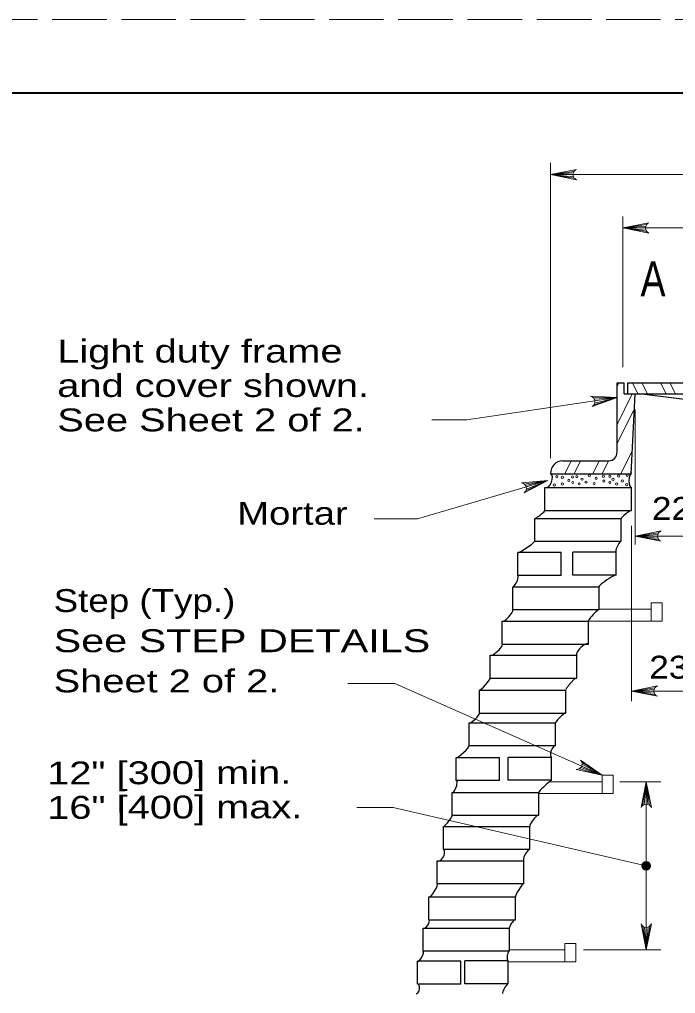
# Model space of a CAD drawing. Extents: x 1083.1 to 1117.1, y 697.4 to 741.4.
# Drawn here: x 1094.35 to 1098.82, y 734.71 to 741.35 of the extents above; entities that cross this region are included whole.
import ezdxf

# ---------------------------------------------------------------- set-up
doc = ezdxf.new("R2010")
doc.units = 0
doc.header["$LTSCALE"] = 0.062
doc.linetypes.add('LONG_DASHED', pattern=[7.5, 6, -1.5])
doc.layers.add('1', color=7, linetype='Continuous', lineweight=13)

msp = doc.modelspace()

# ---------------------------------------------------------------- hatches: boundary and pattern name
at = {"layer": '1'}
msp.add_hatch(color=256, dxfattribs=at).paths.add_polyline_path([(1098.6497, 735.5823, 1), (1098.5907, 735.5823, 1)])

# ---------------------------------------------------------------- linework, layer by layer
at = {"layer": '1', "lineweight": 25}
for p, q in [((1085.12642, 740.85408), (1116.62642, 740.85408)), ((1098.42183, 738.40442), (1098.42183, 738.87625)), ((1098.42183, 738.87625), (1098.4705, 738.87625)), ((1098.4705, 738.80017), (1098.4705, 738.87625)), ((1098.49483, 738.87625), (1100.443, 738.87625)), ((1098.49483, 738.80017), (1098.49483, 738.87625)), ((1098.4705, 738.80017), (1099.43358, 738.80017)), ((1098.51775, 738.25633), (1098.54433, 738.80017)), ((1099.431, 738.692), (1098.57267, 738.80017)), ((1098.051, 738.34442), (1098.36517, 738.34442)), ((1097.96783, 738.25633), (1098.51917, 738.25633)), ((1098.51208, 738.25633), (1098.51917, 738.27067)), ((1098.51917, 738.00592), (1098.51917, 738.16192)), ((1097.93, 738.00592), (1098.51917, 738.00592)), ((1098.44917, 737.79567), (1098.44917, 737.95158)), ((1097.86, 737.79567), (1098.44917, 737.79567)), ((1098.0405, 737.71808), (1097.74592, 737.71808)), ((1097.74592, 737.56217), (1097.74592, 737.71808)), ((1098.0405, 737.56217), (1098.0405, 737.71808)), ((1098.41458, 737.72033), (1098.11992, 737.72033)), ((1098.11992, 737.56442), (1098.11992, 737.72033)), ((1098.41458, 737.56442), (1098.41458, 737.72033)), ((1098.0405, 737.56217), (1097.74592, 737.56217)), ((1098.41458, 737.56442), (1098.11992, 737.56442)), ((1098.29975, 737.329), (1098.29975, 737.48492)), ((1097.7105, 737.329), (1098.29975, 737.329)), ((1098.22783, 737.09467), (1098.22783, 737.25058)), ((1097.63867, 737.09467), (1098.22783, 737.09467)), ((1098.1465, 736.86233), (1098.1465, 737.01825)), ((1097.55725, 736.86233), (1098.1465, 736.86233)), ((1098.07275, 736.62392), (1098.07275, 736.77992)), ((1097.4835, 736.62392), (1098.07275, 736.62392)), ((1098.00275, 736.40167), (1098.00275, 736.55758)), ((1097.4135, 736.40167), (1098.00275, 736.40167)), ((1097.62025, 736.31933), (1097.32567, 736.31933)), ((1097.32567, 736.16333), (1097.32567, 736.31933)), ((1097.62025, 736.16333), (1097.62025, 736.31933)), ((1097.97483, 736.32142), (1097.68025, 736.32142)), ((1097.68025, 736.16542), (1097.68025, 736.32142)), ((1097.97483, 736.16542), (1097.97483, 736.32142)), ((1097.62025, 736.16333), (1097.32567, 736.16333)), ((1097.97483, 736.16542), (1097.68025, 736.16542)), ((1097.88733, 735.92692), (1097.88733, 736.08292)), ((1097.29808, 735.92692), (1097.88733, 735.92692)), ((1097.82683, 735.69458), (1097.82683, 735.85058)), ((1097.23758, 735.69458), (1097.82683, 735.69458)), ((1097.78517, 735.46025), (1097.78517, 735.61625)), ((1097.19592, 735.46025), (1097.78517, 735.46025)), ((1097.72842, 735.21392), (1097.72842, 735.36992)), ((1097.13917, 735.21392), (1097.72842, 735.21392)), ((1097.68867, 735.00158), (1097.68867, 735.15758)), ((1097.0995, 735.00158), (1097.68867, 735.00158)), ((1097.67908, 734.934), (1097.3845, 734.934)), ((1097.3845, 734.778), (1097.3845, 734.934)), ((1097.67908, 734.778), (1097.67908, 734.934)), ((1097.35575, 734.9315), (1097.06108, 734.9315)), ((1097.06108, 734.77558), (1097.06108, 734.9315)), ((1097.35575, 734.77558), (1097.35575, 734.9315)), ((1097.35575, 734.77558), (1097.06108, 734.77558)), ((1097.67908, 734.778), (1097.3845, 734.778))]:
    msp.add_line(p, q, dxfattribs=at)
at = {"layer": '1'}
for p, q in [((1097.96783, 738.36233), (1097.96783, 740.376)), ((1098.128, 740.31817), (1097.96783, 740.29575)), ((1098.12258, 740.30708), (1097.96783, 740.29575)), ((1097.96783, 740.29575), (1099.78475, 740.29575)), ((1098.121, 740.29575), (1097.96783, 740.29575)), ((1098.12383, 740.28133), (1097.96783, 740.29575)), ((1098.12992, 740.27092), (1097.96783, 740.29575)), ((1098.46192, 738.98225), (1098.46192, 740.01133)), ((1098.62217, 739.95508), (1098.46192, 739.93267)), ((1098.61675, 739.944), (1098.46192, 739.93267)), ((1098.61508, 739.93267), (1098.46192, 739.93267)), ((1098.61792, 739.91825), (1098.46192, 739.93267)), ((1098.624, 739.90792), (1098.46192, 739.93267)), ((1098.42183, 738.85092), (1098.43433, 738.87625)), ((1098.56417, 738.80017), (1098.52658, 738.87625)), ((1098.628, 738.80017), (1098.5905, 738.87625)), ((1098.75575, 738.80017), (1098.71825, 738.87625)), ((1098.81967, 738.80017), (1098.78217, 738.87625)), ((1098.42183, 738.59167), (1098.52458, 738.80017)), ((1098.26, 738.77375), (1098.42183, 738.77483)), ((1098.265, 738.72675), (1098.42183, 738.77483)), ((1098.267, 738.7635), (1098.42183, 738.77483)), ((1098.26958, 738.73792), (1098.42183, 738.77483)), ((1098.27033, 738.75258), (1098.42183, 738.77483)), ((1098.42183, 738.462), (1098.5395, 738.70075)), ((1098.54433, 738.69408), (1098.54433, 737.77375)), ((1098.44825, 738.25633), (1098.52542, 738.41292)), ((1098.06492, 738.25633), (1098.10833, 738.34442)), ((1098.12883, 738.25633), (1098.17225, 738.34442)), ((1098.25658, 738.25633), (1098.3, 738.34442)), ((1098.3205, 738.25633), (1098.36392, 738.34442)), ((1097.78875, 738.18575), (1097.94892, 738.20908)), ((1097.79708, 738.17658), (1097.94892, 738.20908)), ((1097.80017, 738.13992), (1097.94892, 738.20908)), ((1097.80183, 738.16617), (1097.94892, 738.20908)), ((1097.80317, 738.15158), (1097.94892, 738.20908)), ((1098.51917, 737.89992), (1098.51917, 736.70442)), ((1098.70458, 737.85292), (1098.54433, 737.8305)), ((1098.69917, 737.84183), (1098.54433, 737.8305)), ((1098.6975, 737.8305), (1098.54433, 737.8305)), ((1098.70033, 737.81608), (1098.54433, 737.8305)), ((1098.70642, 737.80567), (1098.54433, 737.8305)), ((1098.54433, 737.8305), (1100.39208, 737.8305)), ((1098.29975, 737.33133), (1098.6535, 737.33133)), ((1098.6535, 737.25), (1098.6535, 737.37533)), ((1098.729, 737.37533), (1098.6535, 737.37533)), ((1098.729, 737.25), (1098.729, 737.37533)), ((1098.22783, 737.25), (1098.729, 737.25)), ((1098.67942, 736.79592), (1098.51917, 736.77342)), ((1098.674, 736.78475), (1098.51917, 736.77342)), ((1098.67233, 736.77342), (1098.51917, 736.77342)), ((1098.67517, 736.75908), (1098.51917, 736.77342)), ((1098.68133, 736.74867), (1098.51917, 736.77342)), ((1098.51917, 736.77342), (1100.41867, 736.77342)), ((1098.17992, 736.26142), (1098.32008, 736.19958)), ((1098.18175, 736.28775), (1098.32008, 736.19958)), ((1098.18317, 736.27575), (1098.32008, 736.19958)), ((1098.16442, 736.24375), (1098.32008, 736.19958)), ((1098.17383, 736.25175), (1098.32008, 736.19958)), ((1098.32008, 736.07425), (1098.32008, 736.19958)), ((1098.39558, 736.19958), (1098.32008, 736.19958)), ((1098.39558, 736.07425), (1098.39558, 736.19958)), ((1097.9605, 736.15558), (1098.32008, 736.15558)), ((1098.4415, 736.15558), (1098.72033, 736.15558)), ((1098.59542, 735.9935), (1098.62017, 736.15558)), ((1098.60583, 735.99958), (1098.62017, 736.15558)), ((1098.62017, 736.15558), (1098.62017, 735.009)), ((1098.62017, 736.00242), (1098.62017, 736.15558)), ((1098.6315, 736.00083), (1098.62017, 736.15558)), ((1098.64258, 735.99533), (1098.62017, 736.15558)), ((1097.88733, 736.07425), (1098.39558, 736.07425)), ((1098.59775, 735.16925), (1098.62017, 735.009)), ((1098.60883, 735.16383), (1098.62017, 735.009)), ((1098.645, 735.17117), (1098.62017, 735.009)), ((1098.63458, 735.165), (1098.62017, 735.009)), ((1098.62017, 735.16217), (1098.62017, 735.009)), ((1097.68867, 735.009), (1098.06525, 735.009)), ((1098.06525, 734.92767), (1098.06525, 735.05292)), ((1098.14075, 735.05292), (1098.06525, 735.05292)), ((1098.14075, 734.92767), (1098.14075, 735.05292)), ((1098.19317, 735.009), (1098.72033, 735.009)), ((1097.67908, 734.92767), (1098.14075, 734.92767))]:
    msp.add_line(p, q, dxfattribs=at)
at = {"layer": '1', "linetype": 'LONG_DASHED'}
msp.add_lwpolyline([(1083.12642, 719.35408), (1117.12642, 719.35408), (1117.12642, 741.35408), (1083.12642, 741.35408)], close=True, dxfattribs=at)
at = {"layer": '1', "lineweight": 40}
msp.add_lwpolyline([(1085.12642, 740.85408), (1116.62642, 740.85408), (1116.62642, 719.85408), (1085.12642, 719.85408)], close=True, dxfattribs=at)
at = {"layer": '1'}
for points in [[(1098.14483, 740.26033), (1097.96783, 740.29575), (1098.14483, 740.33117)], [(1098.63892, 739.89725), (1098.46192, 739.93267), (1098.63892, 739.96808)], [(1098.46192, 739.93267), (1099.79092, 739.93267), (1100.46742, 739.93267)], [(1098.42183, 738.77483), (1097.39708, 738.62283), (1097.15817, 738.62283)], [(1098.25183, 738.71408), (1098.42183, 738.77483), (1098.24158, 738.78417)], [(1097.94892, 738.20908), (1097.06192, 737.94908), (1096.76567, 737.94908)], [(1097.78892, 738.1255), (1097.94892, 738.20908), (1097.76908, 738.1935)], [(1098.72133, 737.79508), (1098.54433, 737.8305), (1098.72133, 737.86592)], [(1098.32008, 736.19958), (1096.90725, 736.82575), (1096.58683, 736.82575)], [(1098.69617, 736.73808), (1098.51917, 736.77342), (1098.69617, 736.80883)], [(1098.17242, 736.30342), (1098.32008, 736.19958), (1098.14383, 736.23867)], [(1098.58483, 735.97858), (1098.62017, 736.15558), (1098.65558, 735.97858)], [(1098.62017, 735.58233), (1096.89433, 735.979), (1096.64783, 735.979)], [(1098.65558, 735.186), (1098.62017, 735.009), (1098.58483, 735.186)]]:
    msp.add_lwpolyline(points, dxfattribs=at)
at = {"layer": '1', "lineweight": 25}
for points in [[(1097.93, 738.00592), (1097.93, 738.16192), (1098.51917, 738.16192)], [(1097.86, 737.79567), (1097.86, 737.95158), (1098.44917, 737.95158)], [(1097.7105, 737.329), (1097.7105, 737.48492), (1098.29975, 737.48492)], [(1097.63867, 737.09467), (1097.63867, 737.25058), (1098.22783, 737.25058)], [(1097.55725, 736.86233), (1097.55725, 737.01825), (1098.1465, 737.01825)], [(1097.4835, 736.62392), (1097.4835, 736.77992), (1098.07275, 736.77992)], [(1097.4135, 736.40167), (1097.4135, 736.55758), (1098.00275, 736.55758)], [(1097.29808, 735.92692), (1097.29808, 736.08292), (1097.88733, 736.08292)], [(1097.23758, 735.69458), (1097.23758, 735.85058), (1097.82683, 735.85058)], [(1097.19592, 735.46025), (1097.19592, 735.61625), (1097.78517, 735.61625)], [(1097.13917, 735.21392), (1097.13917, 735.36992), (1097.72842, 735.36992)], [(1097.0995, 735.00158), (1097.0995, 735.15758), (1097.68867, 735.15758)]]:
    msp.add_lwpolyline(points, dxfattribs=at)
at = {"layer": '1'}
msp.add_circle((1098.6202, 735.5823), 0.0295, dxfattribs=at)
for centre, start, end in [((1098.15909, 740.29577), 112.08782, 247.91395), ((1098.65319, 739.93272), 112.08782, 247.91395), ((1098.23257, 738.74707), 300.45401, 76.28014), ((1097.76523, 738.15556), 308.35015, 84.17628), ((1098.73562, 737.83052), 112.08782, 247.91395), ((1098.7105, 736.77349), 112.08782, 247.91395), ((1098.14503, 736.27679), 268.26852, 44.09464), ((1098.62024, 735.96432), 22.08782, 157.91395), ((1098.62016, 735.20029), 202.08782, 337.91395)]:
    msp.add_arc(centre, 0.0382, start, end, dxfattribs=at)
at = {"layer": '1', "lineweight": 25}
for centre, major_axis, ratio, start_param, end_param in [((1098.3652, 738.40439), (0, -0.05997), 0.944544, 0.000001, 1.5707952), ((1098.05103, 738.2563), (0, 0.08813), 0.944544, 0.0000048, 1.5708011), ((1097.94888, 738.2091), (0.01807, 0.04755), 0.550574, 3.1091398, 6.2507324), ((1098.5192, 738.2091), (0, -0.0472), 0.356664, 3.1415929, 6.2831855), ((1097.89497, 737.97876), (0.03498, 0.0272), 0.123309, 3.1347753, 6.276368), ((1098.4842, 737.97877), (-0.03499, -0.02719), 0.095152, 3.1363648, 6.2779574), ((1097.80295, 737.75688), (0.05701, 0.03878), 0.08505, 3.1371461, 6.2787387), ((1098.43189, 737.75799), (-0.01723, -0.03769), 0.223335, 3.131028, 6.2726207), ((1097.72822, 737.52355), (0.01758, 0.03869), 0.261975, 3.1289792, 6.2705719), ((1098.35716, 737.52466), (-0.05738, -0.03979), 0.123692, 3.1350238, 6.2766165), ((1097.67457, 737.28977), (0.03579, 0.03934), 0.255117, 3.1260199, 6.2676126), ((1098.26381, 737.28978), (-0.03589, -0.03924), 0.153621, 3.1326147, 6.2742074), ((1097.59795, 737.05644), (0.04053, 0.03834), 0.248819, 3.1265579, 6.2681506), ((1098.18719, 737.05644), (0.04038, 0.03851), 0.348106, 6.2607285, 9.4023212), ((1097.52039, 736.8211), (0.03686, 0.04122), 0.109562, 3.1352712, 6.2768638), ((1097.4485, 736.59077), (0.03491, 0.03328), 0.214158, 3.1288563, 6.2704489), ((1098.03774, 736.59077), (-0.03496, -0.03322), 0.136714, 3.1336877, 6.2752804), ((1097.36957, 736.36047), (0.04388, 0.04122), 0.144657, 3.1332208, 6.2748134), ((1097.98881, 736.36151), (-0.01364, -0.04023), 0.407354, 3.1235301, 6.2651227), ((1097.31187, 736.12314), (-0.01358, -0.0403), 0.335589, 6.2693556, 9.4109483), ((1097.93111, 736.12417), (-0.04376, -0.04127), 0.064605, 3.137914, 6.2795067), ((1097.85707, 735.88876), (-0.03017, -0.03827), 0.209512, 3.1292724, 6.2708651), ((1097.26784, 735.88876), (0.03023, 0.03822), 0.136372, 3.1337805, 6.2753732), ((1097.21676, 735.65543), (0.02002, 0.03962), 0.541644, 3.1041747, 6.2457674), ((1097.80599, 735.65543), (-0.02067, -0.03927), 0.264991, 3.1276914, 6.2692841), ((1097.16757, 735.41508), (0.02825, 0.04528), 0.223655, 3.1291999, 6.2707925), ((1097.75681, 735.41508), (-0.02834, -0.04523), 0.13218, 3.1345117, 6.2761043), ((1097.11933, 735.18575), (0.01952, 0.02843), 0.429767, 3.112728, 6.2543206), ((1097.70856, 735.18575), (-0.0198, -0.02822), 0.206426, 3.1297914, 6.2713841), ((1097.08028, 734.96658), (0.01897, 0.03516), 0.327378, 3.123429, 6.2650216), ((1097.68389, 734.96779), (-0.00474, -0.03384), 0.324121, 3.1355093, 6.277102), ((1097.05664, 734.74326), (0.00425, 0.03236), 0.53803, 3.1292062, 6.2707989), ((1097.66025, 734.74448), (-0.01879, -0.03357), 0.173986, 3.1325933, 6.274186)]:
    msp.add_ellipse(centre, major_axis=major_axis, ratio=ratio, start_param=start_param, end_param=end_param, dxfattribs=at)
at = {"layer": '1'}
for centre in [(1098.49026, 738.24594), (1097.99363, 738.17963), (1098.01115, 738.23586), (1098.04849, 738.18506), (1098.04877, 738.2315), (1098.09251, 738.21089), (1098.11733, 738.23394), (1098.11984, 738.19619), (1098.1475, 738.23664), (1098.16365, 738.18719), (1098.18304, 738.21899), (1098.21033, 738.19849), (1098.23252, 738.24188), (1098.2651, 738.18941), (1098.27902, 738.22415), (1098.32845, 738.23833), (1098.33101, 738.20638), (1098.37208, 738.1974), (1098.37232, 738.23803), (1098.39413, 738.21756), (1098.41861, 738.18547), (1098.43265, 738.24053), (1098.45711, 738.20553), (1098.48713, 738.18211)]:
    msp.add_ellipse(centre, major_axis=(0, 0.00779), ratio=0.944544, dxfattribs=at)
msp.add_ellipse((1098.10963, 736.8211), major_axis=(-0.03683, -0.04125), ratio=0.157731, start_param=3.1323715, end_param=6.2739642, dxfattribs=at)

# ---------------------------------------------------------------- texts
for s, height, width, p in [('A', 0.24, 0.8, (1098.58117, 739.46475)), ('Light duty frame', 0.156, 1.3, (1094.60558, 739.01425)), ('and cover shown.', 0.156, 1.3, (1094.60558, 738.77958)), ('See Sheet 2 of 2.', 0.156, 1.3, (1094.60558, 738.54492)), ('Mortar', 0.156, 1.25, (1095.83233, 737.90808)), ('22 1/2" [572]', 0.156, 1.15, (1098.659, 737.94108)), ('Step (Typ.)', 0.156, 1.2, (1094.581, 737.31292)), ('See STEP DETAILS', 0.156, 1.35, (1094.581, 737.03892)), ('23 3/4" [600]', 0.156, 1.15, (1098.64092, 736.85858)), ('Sheet 2 of 2.', 0.156, 1.3, (1094.581, 736.76492))]:
    msp.add_text(s, height=height, dxfattribs=dict(at, width=width)).set_placement(p)
at = {"layer": '1', "width": 1.3}
for s, p in [('12" [300] min.', (1094.53667, 736.1365)), ('16" [400] max.', (1094.53733, 735.90183))]:
    msp.add_text(s, height=0.156, rotation=0.169, dxfattribs=at).set_placement(p)

doc.saveas('drawing.dxf')
